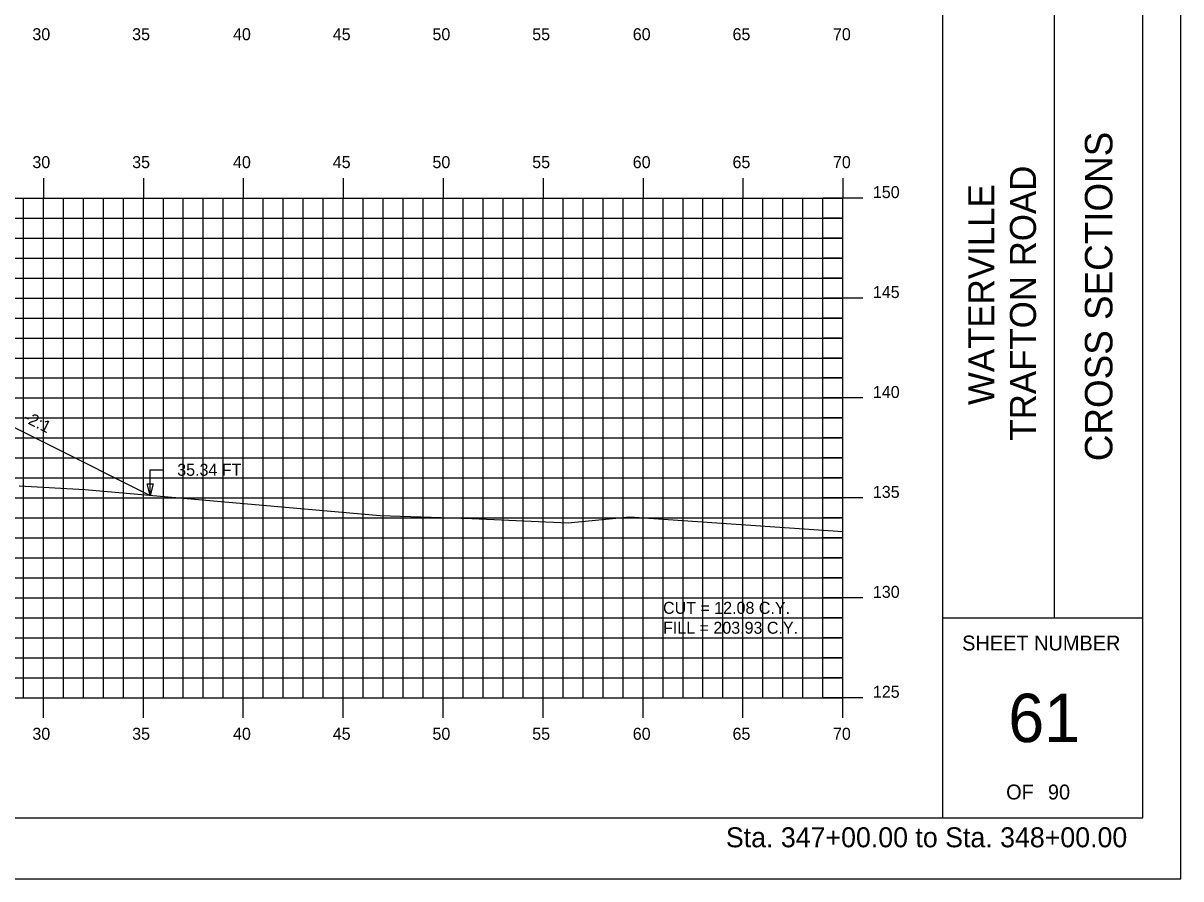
# Model space of a CAD drawing. Extents: x 1144085 to 1144255, y 608981 to 609091.
# Drawn here: x 1144197.3 to 1144255.3, y 608981.3 to 609024.1 of the extents above; entities that cross this region are included whole.
import ezdxf

# ---------------------------------------------------------------- set-up
doc = ezdxf.new("R2010")
doc.units = 0
for name, color, linetype in [('ANNOTATION', 7, 'Continuous'), ('BORDER', 7, 'Continuous'), ('D_Roadway_SlopeLines', 7, 'Continuous'), ('D_Text_Standard', 7, 'Continuous'), ('H_V ANNOTATION', 7, 'Continuous'), ('HIGHWAY_TITLE', 7, 'Continuous'), ('MAJOR', 7, 'Continuous'), ('MINOR', 7, 'Continuous'), ('PLOT BOUNDARY', 7, 'Continuous'), ('S_Roadway_Centerline', 7, 'Continuous')]:
    doc.layers.add(name, color=color, linetype=linetype)

msp = doc.modelspace()

# ---------------------------------------------------------------- linework, layer by layer
msp.add_lwpolyline([(1144134.957, 609003.69), (1144138.826, 609005.625), (1144142.826, 609006.625), (1144153.348, 609009.255), (1144153.349, 609009.255), (1144157.349, 609009.415), (1144168.349, 609009.635), (1144179.349, 609009.415), (1144186.349, 609009.135), (1144191.266, 609006.677), (1144193.266, 609005.677), (1144203.692, 609000.464)])
at = {"layer": 'BORDER'}
for p, q in [((1144243.349, 608984.335), (1144243.349, 609089.335)), ((1144248.94, 608994.338), (1144248.94, 609029.338)), ((1144243.349, 608994.338), (1144253.349, 608994.338))]:
    msp.add_line(p, q, dxfattribs=at)
msp.add_lwpolyline([(1144093.349, 608984.335), (1144253.349, 608984.335), (1144253.349, 609089.335), (1144093.349, 609089.335)], close=True, dxfattribs=at)
at = {"layer": 'D_Roadway_SlopeLines'}
msp.add_lwpolyline([(1144193.266, 609005.677), (1144203.692, 609000.464)], dxfattribs=at)
at = {"layer": 'D_Text_Standard'}
msp.add_lwpolyline([(1144203.692, 609000.464), (1144203.684, 609001.742), (1144204.364, 609001.742)], dxfattribs=at)
msp.add_lwpolyline([(1144203.692, 609000.464), (1144203.543, 609001.045), (1144203.834, 609001.047)], close=True, dxfattribs=at)
at = {"layer": 'MAJOR'}
for p, q in [((1144198.349, 609016.337), (1144198.349, 609015.335)), ((1144203.349, 609016.337), (1144203.349, 609015.335)), ((1144208.349, 609016.337), (1144208.349, 609015.335)), ((1144213.349, 609016.337), (1144213.349, 609015.335)), ((1144218.349, 609016.337), (1144218.349, 609015.335)), ((1144223.349, 609016.337), (1144223.349, 609015.335)), ((1144228.349, 609016.337), (1144228.349, 609015.335)), ((1144233.349, 609016.337), (1144233.349, 609015.335)), ((1144238.349, 609016.337), (1144238.349, 609015.335)), ((1144098.349, 609015.335), (1144238.349, 609015.335)), ((1144098.349, 609015.335), (1144238.349, 609015.335)), ((1144198.349, 608990.335), (1144198.349, 609015.335)), ((1144203.349, 608990.335), (1144203.349, 609015.335)), ((1144208.349, 608990.335), (1144208.349, 609015.335)), ((1144213.349, 608990.335), (1144213.349, 609015.335)), ((1144218.349, 608990.335), (1144218.349, 609015.335)), ((1144223.349, 608990.335), (1144223.349, 609015.335)), ((1144228.349, 608990.335), (1144228.349, 609015.335)), ((1144233.349, 608990.335), (1144233.349, 609015.335)), ((1144239.351, 609015.335), (1144237.347, 609015.335)), ((1144238.349, 608990.335), (1144238.349, 609015.335)), ((1144238.349, 608990.335), (1144238.349, 609015.335)), ((1144098.349, 609010.335), (1144238.349, 609010.335)), ((1144239.351, 609010.335), (1144237.347, 609010.335)), ((1144098.349, 609005.335), (1144238.349, 609005.335)), ((1144239.351, 609005.335), (1144237.347, 609005.335)), ((1144098.349, 609000.335), (1144238.349, 609000.335)), ((1144239.351, 609000.335), (1144237.347, 609000.335)), ((1144098.349, 608995.335), (1144238.349, 608995.335)), ((1144239.351, 608995.335), (1144237.347, 608995.335)), ((1144098.349, 608990.335), (1144238.349, 608990.335)), ((1144098.349, 608990.335), (1144238.349, 608990.335)), ((1144198.349, 608989.333), (1144198.349, 608990.335)), ((1144203.349, 608989.333), (1144203.349, 608990.335)), ((1144208.349, 608989.333), (1144208.349, 608990.335)), ((1144213.349, 608989.333), (1144213.349, 608990.335)), ((1144218.349, 608989.333), (1144218.349, 608990.335)), ((1144223.349, 608989.333), (1144223.349, 608990.335)), ((1144228.349, 608989.333), (1144228.349, 608990.335)), ((1144233.349, 608989.333), (1144233.349, 608990.335)), ((1144239.351, 608990.335), (1144237.347, 608990.335)), ((1144238.349, 608989.333), (1144238.349, 608990.335))]:
    msp.add_line(p, q, dxfattribs=at)
at = {"layer": 'MINOR'}
for p, q in [((1144197.349, 608990.335), (1144197.349, 609015.335)), ((1144199.349, 608990.335), (1144199.349, 609015.335)), ((1144200.349, 608990.335), (1144200.349, 609015.335)), ((1144201.349, 608990.335), (1144201.349, 609015.335)), ((1144202.349, 608990.335), (1144202.349, 609015.335)), ((1144204.349, 608990.335), (1144204.349, 609015.335)), ((1144205.349, 608990.335), (1144205.349, 609015.335)), ((1144206.349, 608990.335), (1144206.349, 609015.335)), ((1144207.349, 608990.335), (1144207.349, 609015.335)), ((1144209.349, 608990.335), (1144209.349, 609015.335)), ((1144210.349, 608990.335), (1144210.349, 609015.335)), ((1144211.349, 608990.335), (1144211.349, 609015.335)), ((1144212.349, 608990.335), (1144212.349, 609015.335)), ((1144214.349, 608990.335), (1144214.349, 609015.335)), ((1144215.349, 608990.335), (1144215.349, 609015.335)), ((1144216.349, 608990.335), (1144216.349, 609015.335)), ((1144217.349, 608990.335), (1144217.349, 609015.335)), ((1144219.349, 608990.335), (1144219.349, 609015.335)), ((1144220.349, 608990.335), (1144220.349, 609015.335)), ((1144221.349, 608990.335), (1144221.349, 609015.335)), ((1144222.349, 608990.335), (1144222.349, 609015.335)), ((1144224.349, 608990.335), (1144224.349, 609015.335)), ((1144225.349, 608990.335), (1144225.349, 609015.335)), ((1144226.349, 608990.335), (1144226.349, 609015.335)), ((1144227.349, 608990.335), (1144227.349, 609015.335)), ((1144229.349, 608990.335), (1144229.349, 609015.335)), ((1144230.349, 608990.335), (1144230.349, 609015.335)), ((1144231.349, 608990.335), (1144231.349, 609015.335)), ((1144232.349, 608990.335), (1144232.349, 609015.335)), ((1144234.349, 608990.335), (1144234.349, 609015.335)), ((1144235.349, 608990.335), (1144235.349, 609015.335)), ((1144236.349, 608990.335), (1144236.349, 609015.335)), ((1144237.349, 608990.335), (1144237.349, 609015.335)), ((1144098.349, 609014.335), (1144238.349, 609014.335)), ((1144238.349, 609014.335), (1144237.347, 609014.335)), ((1144098.349, 609013.335), (1144238.349, 609013.335)), ((1144238.349, 609013.335), (1144237.347, 609013.335)), ((1144098.349, 609012.335), (1144238.349, 609012.335)), ((1144238.349, 609012.335), (1144237.347, 609012.335)), ((1144098.349, 609011.335), (1144238.349, 609011.335)), ((1144238.349, 609011.335), (1144237.347, 609011.335)), ((1144098.349, 609009.335), (1144238.349, 609009.335)), ((1144238.349, 609009.335), (1144237.347, 609009.335)), ((1144098.349, 609008.335), (1144238.349, 609008.335)), ((1144238.349, 609008.335), (1144237.347, 609008.335)), ((1144098.349, 609007.335), (1144238.349, 609007.335)), ((1144238.349, 609007.335), (1144237.347, 609007.335)), ((1144098.349, 609006.335), (1144238.349, 609006.335)), ((1144238.349, 609006.335), (1144237.347, 609006.335)), ((1144098.349, 609004.335), (1144238.349, 609004.335)), ((1144238.349, 609004.335), (1144237.347, 609004.335)), ((1144098.349, 609003.335), (1144238.349, 609003.335)), ((1144238.349, 609003.335), (1144237.347, 609003.335)), ((1144098.349, 609002.335), (1144238.349, 609002.335)), ((1144238.349, 609002.335), (1144237.347, 609002.335)), ((1144098.349, 609001.335), (1144238.349, 609001.335)), ((1144238.349, 609001.335), (1144237.347, 609001.335)), ((1144098.349, 608999.335), (1144238.349, 608999.335)), ((1144238.349, 608999.335), (1144237.347, 608999.335)), ((1144098.349, 608998.335), (1144238.349, 608998.335)), ((1144238.349, 608998.335), (1144237.347, 608998.335)), ((1144098.349, 608997.335), (1144238.349, 608997.335)), ((1144238.349, 608997.335), (1144237.347, 608997.335)), ((1144098.349, 608996.335), (1144238.349, 608996.335)), ((1144238.349, 608996.335), (1144237.347, 608996.335)), ((1144098.349, 608994.335), (1144238.349, 608994.335)), ((1144238.349, 608994.335), (1144237.347, 608994.335)), ((1144098.349, 608993.335), (1144238.349, 608993.335)), ((1144238.349, 608993.335), (1144237.347, 608993.335)), ((1144098.349, 608992.335), (1144238.349, 608992.335)), ((1144238.349, 608992.335), (1144237.347, 608992.335)), ((1144098.349, 608991.335), (1144238.349, 608991.335)), ((1144238.349, 608991.335), (1144237.347, 608991.335))]:
    msp.add_line(p, q, dxfattribs=at)
at = {"layer": 'PLOT BOUNDARY'}
msp.add_lwpolyline([(1144085.256, 608981.276), (1144255.256, 608981.276), (1144255.256, 609091.276), (1144085.256, 609091.276)], close=True, dxfattribs=at)
at = {"layer": 'S_Roadway_Centerline'}
msp.add_lwpolyline([(1144197.135, 609000.938), (1144200.427, 609000.749), (1144215.192, 608999.459), (1144219.789, 608999.308), (1144224.596, 608999.089), (1144227.671, 608999.392), (1144238.349, 608998.651)], dxfattribs=at)

# ---------------------------------------------------------------- texts
at = {"layer": 'ANNOTATION'}
msp.add_text('-2:1', height=0.6, rotation=333.43495, dxfattribs=at).set_placement((1144197.302, 609004.177))
at = {"layer": 'BORDER'}
msp.add_text('CROSS SECTIONS', height=1.37787, rotation=90, dxfattribs=at).set_placement((1144251.834, 609002.172))
for s, height, p in [('SHEET NUMBER', 0.74527, (1144244.315, 608992.701)), ('61', 2.4194, (1144246.621, 608988.118)), ('OF', 0.7453, (1144246.516, 608985.248)), ('90', 0.7453, (1144248.606, 608985.248))]:
    msp.add_text(s, height=height, dxfattribs=at).set_placement(p)
at = {"layer": 'D_Text_Standard'}
for s, p in [('35.34 FT', (1144205.044, 609001.442)), ('CUT = 12.08 C.Y.', (1144229.349, 608994.535)), ('FILL = 203.93 C.Y.', (1144229.349, 608993.539))]:
    msp.add_text(s, height=0.6, dxfattribs=at).set_placement(p)
at = {"layer": 'H_V ANNOTATION'}
for s, height, p in [('30', 0.6, (1144197.798, 609023.235)), ('35', 0.6, (1144202.79, 609023.235)), ('40', 0.6, (1144207.835, 609023.235)), ('45', 0.6, (1144212.827, 609023.235)), ('50', 0.6, (1144217.814, 609023.235)), ('55', 0.6, (1144222.806, 609023.235)), ('60', 0.6, (1144227.835, 609023.235)), ('65', 0.6, (1144232.827, 609023.235)), ('70', 0.6, (1144237.851, 609023.235)), ('30', 0.6, (1144197.798, 609016.835)), ('35', 0.6, (1144202.79, 609016.835)), ('40', 0.6, (1144207.835, 609016.835)), ('45', 0.6, (1144212.827, 609016.835)), ('50', 0.6, (1144217.814, 609016.835)), ('55', 0.6, (1144222.806, 609016.835)), ('60', 0.6, (1144227.835, 609016.835)), ('65', 0.6, (1144232.827, 609016.835)), ('70', 0.6, (1144237.851, 609016.835)), ('150', 0.6, (1144239.849, 609015.335)), ('145', 0.6, (1144239.849, 609010.335)), ('140', 0.6, (1144239.849, 609005.335)), ('135', 0.6, (1144239.849, 609000.335)), ('130', 0.6, (1144239.849, 608995.335)), ('125', 0.6, (1144239.849, 608990.335)), ('30', 0.6, (1144197.798, 608988.235)), ('35', 0.6, (1144202.79, 608988.235)), ('40', 0.6, (1144207.835, 608988.235)), ('45', 0.6, (1144212.827, 608988.235)), ('50', 0.6, (1144217.814, 608988.235)), ('55', 0.6, (1144222.806, 608988.235)), ('60', 0.6, (1144227.835, 608988.235)), ('65', 0.6, (1144232.827, 608988.235)), ('70', 0.6, (1144237.851, 608988.235)), ('Sta. 347+00.00 to Sta. 348+00.00', 1.0002, (1144232.495, 608982.855))]:
    msp.add_text(s, height=height, dxfattribs=at).set_placement(p)
at = {"layer": 'HIGHWAY_TITLE'}
for s, height, p in [('TRAFTON ROAD', 1.30428, (1144248.009, 609003.201)), ('WATERVILLE', 1.3043, (1144245.922, 609004.98))]:
    msp.add_text(s, height=height, rotation=90, dxfattribs=at).set_placement(p)

doc.saveas('drawing.dxf')
